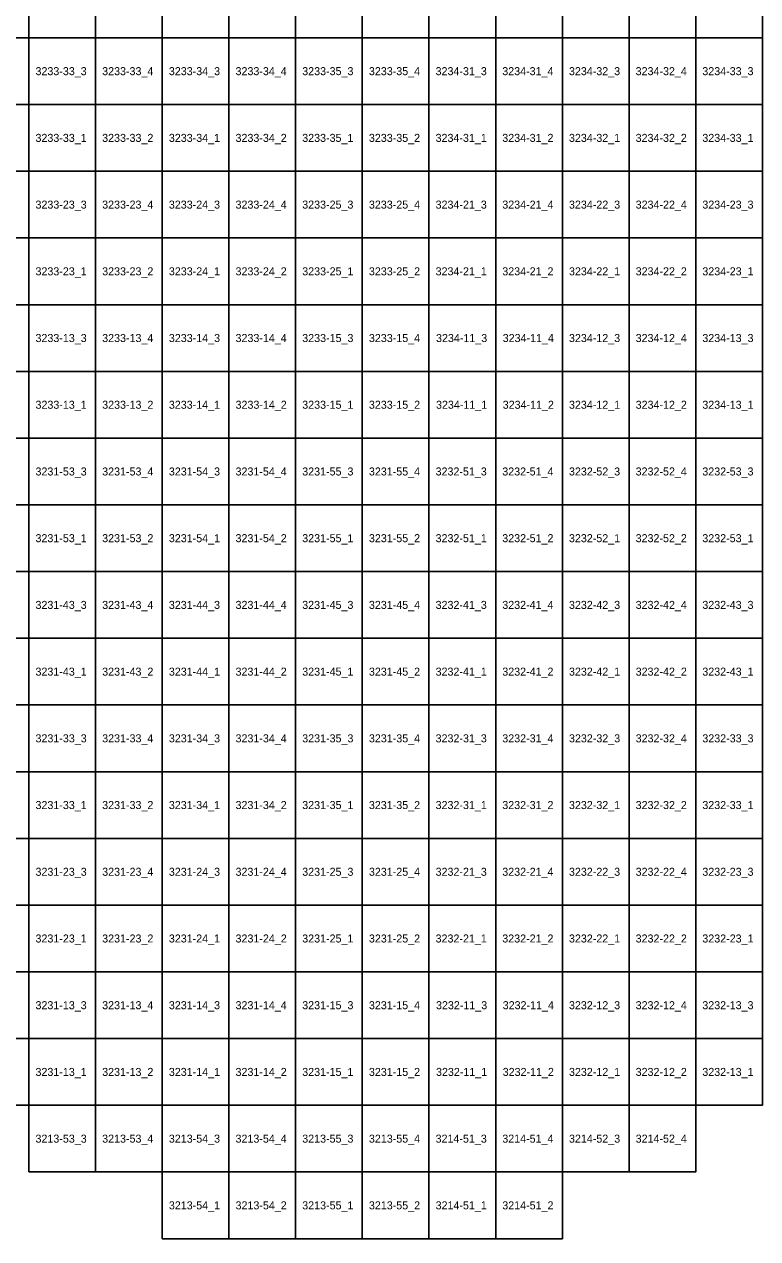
# Model space of a CAD drawing. Extents: x 312500 to 765000, y 172500 to 440000.
# Drawn here: x 409827 to 437325, y 245000 to 290507 of the extents above; entities that cross this region are included whole.
import ezdxf

# ---------------------------------------------------------------- set-up
doc = ezdxf.new("R2010")
doc.units = 0
doc.layers.add('Topo5_ramis_TKS2025', color=7, linetype='Continuous')
doc.layers.add('Topo5_ramis_TKS2025_Nr', color=7, linetype='Continuous')

msp = doc.modelspace()

# ---------------------------------------------------------------- linework, layer by layer
at = {"layer": 'Topo5_ramis_TKS2025'}
for points in [[(407500, 290000), (407500, 292500), (410000, 292500), (410000, 290000), (407500, 290000)], [(410000, 290000), (410000, 292500), (412500, 292500), (412500, 290000), (410000, 290000)], [(412500, 290000), (412500, 292500), (415000, 292500), (415000, 290000), (412500, 290000)], [(415000, 290000), (415000, 292500), (417500, 292500), (417500, 290000), (415000, 290000)], [(417500, 290000), (417500, 292500), (420000, 292500), (420000, 290000), (417500, 290000)], [(420000, 290000), (420000, 292500), (422500, 292500), (422500, 290000), (420000, 290000)], [(422500, 290000), (422500, 292500), (425000, 292500), (425000, 290000), (422500, 290000)], [(425000, 290000), (425000, 292500), (427500, 292500), (427500, 290000), (425000, 290000)], [(427500, 290000), (427500, 292500), (430000, 292500), (430000, 290000), (427500, 290000)], [(430000, 290000), (430000, 292500), (432500, 292500), (432500, 290000), (430000, 290000)], [(432500, 290000), (432500, 292500), (435000, 292500), (435000, 290000), (432500, 290000)], [(435000, 290000), (435000, 292500), (437500, 292500), (437500, 290000), (435000, 290000)], [(407500, 287500), (407500, 290000), (410000, 290000), (410000, 287500), (407500, 287500)], [(410000, 287500), (410000, 290000), (412500, 290000), (412500, 287500), (410000, 287500)], [(412500, 287500), (412500, 290000), (415000, 290000), (415000, 287500), (412500, 287500)], [(415000, 287500), (415000, 290000), (417500, 290000), (417500, 287500), (415000, 287500)], [(417500, 287500), (417500, 290000), (420000, 290000), (420000, 287500), (417500, 287500)], [(420000, 287500), (420000, 290000), (422500, 290000), (422500, 287500), (420000, 287500)], [(422500, 287500), (422500, 290000), (425000, 290000), (425000, 287500), (422500, 287500)], [(425000, 287500), (425000, 290000), (427500, 290000), (427500, 287500), (425000, 287500)], [(427500, 287500), (427500, 290000), (430000, 290000), (430000, 287500), (427500, 287500)], [(430000, 287500), (430000, 290000), (432500, 290000), (432500, 287500), (430000, 287500)], [(432500, 287500), (432500, 290000), (435000, 290000), (435000, 287500), (432500, 287500)], [(435000, 287500), (435000, 290000), (437500, 290000), (437500, 287500), (435000, 287500)], [(407500, 285000), (407500, 287500), (410000, 287500), (410000, 285000), (407500, 285000)], [(410000, 285000), (410000, 287500), (412500, 287500), (412500, 285000), (410000, 285000)], [(412500, 285000), (412500, 287500), (415000, 287500), (415000, 285000), (412500, 285000)], [(415000, 285000), (415000, 287500), (417500, 287500), (417500, 285000), (415000, 285000)], [(417500, 285000), (417500, 287500), (420000, 287500), (420000, 285000), (417500, 285000)], [(420000, 285000), (420000, 287500), (422500, 287500), (422500, 285000), (420000, 285000)], [(422500, 285000), (422500, 287500), (425000, 287500), (425000, 285000), (422500, 285000)], [(425000, 285000), (425000, 287500), (427500, 287500), (427500, 285000), (425000, 285000)], [(427500, 285000), (427500, 287500), (430000, 287500), (430000, 285000), (427500, 285000)], [(430000, 285000), (430000, 287500), (432500, 287500), (432500, 285000), (430000, 285000)], [(432500, 285000), (432500, 287500), (435000, 287500), (435000, 285000), (432500, 285000)], [(435000, 285000), (435000, 287500), (437500, 287500), (437500, 285000), (435000, 285000)], [(407500, 282500), (407500, 285000), (410000, 285000), (410000, 282500), (407500, 282500)], [(410000, 282500), (410000, 285000), (412500, 285000), (412500, 282500), (410000, 282500)], [(412500, 282500), (412500, 285000), (415000, 285000), (415000, 282500), (412500, 282500)], [(415000, 282500), (415000, 285000), (417500, 285000), (417500, 282500), (415000, 282500)], [(417500, 282500), (417500, 285000), (420000, 285000), (420000, 282500), (417500, 282500)], [(420000, 282500), (420000, 285000), (422500, 285000), (422500, 282500), (420000, 282500)], [(422500, 282500), (422500, 285000), (425000, 285000), (425000, 282500), (422500, 282500)], [(425000, 282500), (425000, 285000), (427500, 285000), (427500, 282500), (425000, 282500)], [(427500, 282500), (427500, 285000), (430000, 285000), (430000, 282500), (427500, 282500)], [(430000, 282500), (430000, 285000), (432500, 285000), (432500, 282500), (430000, 282500)], [(432500, 282500), (432500, 285000), (435000, 285000), (435000, 282500), (432500, 282500)], [(435000, 282500), (435000, 285000), (437500, 285000), (437500, 282500), (435000, 282500)], [(407500, 280000), (407500, 282500), (410000, 282500), (410000, 280000), (407500, 280000)], [(410000, 280000), (410000, 282500), (412500, 282500), (412500, 280000), (410000, 280000)], [(412500, 280000), (412500, 282500), (415000, 282500), (415000, 280000), (412500, 280000)], [(415000, 280000), (415000, 282500), (417500, 282500), (417500, 280000), (415000, 280000)], [(417500, 280000), (417500, 282500), (420000, 282500), (420000, 280000), (417500, 280000)], [(420000, 280000), (420000, 282500), (422500, 282500), (422500, 280000), (420000, 280000)], [(422500, 280000), (422500, 282500), (425000, 282500), (425000, 280000), (422500, 280000)], [(425000, 280000), (425000, 282500), (427500, 282500), (427500, 280000), (425000, 280000)], [(427500, 280000), (427500, 282500), (430000, 282500), (430000, 280000), (427500, 280000)], [(430000, 280000), (430000, 282500), (432500, 282500), (432500, 280000), (430000, 280000)], [(432500, 280000), (432500, 282500), (435000, 282500), (435000, 280000), (432500, 280000)], [(435000, 280000), (435000, 282500), (437500, 282500), (437500, 280000), (435000, 280000)], [(407500, 277500), (407500, 280000), (410000, 280000), (410000, 277500), (407500, 277500)], [(410000, 277500), (410000, 280000), (412500, 280000), (412500, 277500), (410000, 277500)], [(412500, 277500), (412500, 280000), (415000, 280000), (415000, 277500), (412500, 277500)], [(415000, 277500), (415000, 280000), (417500, 280000), (417500, 277500), (415000, 277500)], [(417500, 277500), (417500, 280000), (420000, 280000), (420000, 277500), (417500, 277500)], [(420000, 277500), (420000, 280000), (422500, 280000), (422500, 277500), (420000, 277500)], [(422500, 277500), (422500, 280000), (425000, 280000), (425000, 277500), (422500, 277500)], [(425000, 277500), (425000, 280000), (427500, 280000), (427500, 277500), (425000, 277500)], [(427500, 277500), (427500, 280000), (430000, 280000), (430000, 277500), (427500, 277500)], [(430000, 277500), (430000, 280000), (432500, 280000), (432500, 277500), (430000, 277500)], [(432500, 277500), (432500, 280000), (435000, 280000), (435000, 277500), (432500, 277500)], [(435000, 277500), (435000, 280000), (437500, 280000), (437500, 277500), (435000, 277500)], [(407500, 275000), (407500, 277500), (410000, 277500), (410000, 275000), (407500, 275000)], [(410000, 275000), (410000, 277500), (412500, 277500), (412500, 275000), (410000, 275000)], [(412500, 275000), (412500, 277500), (415000, 277500), (415000, 275000), (412500, 275000)], [(415000, 275000), (415000, 277500), (417500, 277500), (417500, 275000), (415000, 275000)], [(417500, 275000), (417500, 277500), (420000, 277500), (420000, 275000), (417500, 275000)], [(420000, 275000), (420000, 277500), (422500, 277500), (422500, 275000), (420000, 275000)], [(422500, 275000), (422500, 277500), (425000, 277500), (425000, 275000), (422500, 275000)], [(425000, 275000), (425000, 277500), (427500, 277500), (427500, 275000), (425000, 275000)], [(427500, 275000), (427500, 277500), (430000, 277500), (430000, 275000), (427500, 275000)], [(430000, 275000), (430000, 277500), (432500, 277500), (432500, 275000), (430000, 275000)], [(432500, 275000), (432500, 277500), (435000, 277500), (435000, 275000), (432500, 275000)], [(435000, 275000), (435000, 277500), (437500, 277500), (437500, 275000), (435000, 275000)], [(407500, 272500), (407500, 275000), (410000, 275000), (410000, 272500), (407500, 272500)], [(410000, 272500), (410000, 275000), (412500, 275000), (412500, 272500), (410000, 272500)], [(412500, 272500), (412500, 275000), (415000, 275000), (415000, 272500), (412500, 272500)], [(415000, 272500), (415000, 275000), (417500, 275000), (417500, 272500), (415000, 272500)], [(417500, 272500), (417500, 275000), (420000, 275000), (420000, 272500), (417500, 272500)], [(420000, 272500), (420000, 275000), (422500, 275000), (422500, 272500), (420000, 272500)], [(422500, 272500), (422500, 275000), (425000, 275000), (425000, 272500), (422500, 272500)], [(425000, 272500), (425000, 275000), (427500, 275000), (427500, 272500), (425000, 272500)], [(427500, 272500), (427500, 275000), (430000, 275000), (430000, 272500), (427500, 272500)], [(430000, 272500), (430000, 275000), (432500, 275000), (432500, 272500), (430000, 272500)], [(432500, 272500), (432500, 275000), (435000, 275000), (435000, 272500), (432500, 272500)], [(435000, 272500), (435000, 275000), (437500, 275000), (437500, 272500), (435000, 272500)], [(407500, 270000), (407500, 272500), (410000, 272500), (410000, 270000), (407500, 270000)], [(410000, 270000), (410000, 272500), (412500, 272500), (412500, 270000), (410000, 270000)], [(412500, 270000), (412500, 272500), (415000, 272500), (415000, 270000), (412500, 270000)], [(415000, 270000), (415000, 272500), (417500, 272500), (417500, 270000), (415000, 270000)], [(417500, 270000), (417500, 272500), (420000, 272500), (420000, 270000), (417500, 270000)], [(420000, 270000), (420000, 272500), (422500, 272500), (422500, 270000), (420000, 270000)], [(422500, 270000), (422500, 272500), (425000, 272500), (425000, 270000), (422500, 270000)], [(425000, 270000), (425000, 272500), (427500, 272500), (427500, 270000), (425000, 270000)], [(427500, 270000), (427500, 272500), (430000, 272500), (430000, 270000), (427500, 270000)], [(430000, 270000), (430000, 272500), (432500, 272500), (432500, 270000), (430000, 270000)], [(432500, 270000), (432500, 272500), (435000, 272500), (435000, 270000), (432500, 270000)], [(435000, 270000), (435000, 272500), (437500, 272500), (437500, 270000), (435000, 270000)], [(407500, 267500), (407500, 270000), (410000, 270000), (410000, 267500), (407500, 267500)], [(410000, 267500), (410000, 270000), (412500, 270000), (412500, 267500), (410000, 267500)], [(412500, 267500), (412500, 270000), (415000, 270000), (415000, 267500), (412500, 267500)], [(415000, 267500), (415000, 270000), (417500, 270000), (417500, 267500), (415000, 267500)], [(417500, 267500), (417500, 270000), (420000, 270000), (420000, 267500), (417500, 267500)], [(420000, 267500), (420000, 270000), (422500, 270000), (422500, 267500), (420000, 267500)], [(422500, 267500), (422500, 270000), (425000, 270000), (425000, 267500), (422500, 267500)], [(425000, 267500), (425000, 270000), (427500, 270000), (427500, 267500), (425000, 267500)], [(427500, 267500), (427500, 270000), (430000, 270000), (430000, 267500), (427500, 267500)], [(430000, 267500), (430000, 270000), (432500, 270000), (432500, 267500), (430000, 267500)], [(432500, 267500), (432500, 270000), (435000, 270000), (435000, 267500), (432500, 267500)], [(435000, 267500), (435000, 270000), (437500, 270000), (437500, 267500), (435000, 267500)], [(407500, 265000), (407500, 267500), (410000, 267500), (410000, 265000), (407500, 265000)], [(410000, 265000), (410000, 267500), (412500, 267500), (412500, 265000), (410000, 265000)], [(412500, 265000), (412500, 267500), (415000, 267500), (415000, 265000), (412500, 265000)], [(415000, 265000), (415000, 267500), (417500, 267500), (417500, 265000), (415000, 265000)], [(417500, 265000), (417500, 267500), (420000, 267500), (420000, 265000), (417500, 265000)], [(420000, 265000), (420000, 267500), (422500, 267500), (422500, 265000), (420000, 265000)], [(422500, 265000), (422500, 267500), (425000, 267500), (425000, 265000), (422500, 265000)], [(425000, 265000), (425000, 267500), (427500, 267500), (427500, 265000), (425000, 265000)], [(427500, 265000), (427500, 267500), (430000, 267500), (430000, 265000), (427500, 265000)], [(430000, 265000), (430000, 267500), (432500, 267500), (432500, 265000), (430000, 265000)], [(432500, 265000), (432500, 267500), (435000, 267500), (435000, 265000), (432500, 265000)], [(435000, 265000), (435000, 267500), (437500, 267500), (437500, 265000), (435000, 265000)], [(407500, 262500), (407500, 265000), (410000, 265000), (410000, 262500), (407500, 262500)], [(410000, 262500), (410000, 265000), (412500, 265000), (412500, 262500), (410000, 262500)], [(412500, 262500), (412500, 265000), (415000, 265000), (415000, 262500), (412500, 262500)], [(415000, 262500), (415000, 265000), (417500, 265000), (417500, 262500), (415000, 262500)], [(417500, 262500), (417500, 265000), (420000, 265000), (420000, 262500), (417500, 262500)], [(420000, 262500), (420000, 265000), (422500, 265000), (422500, 262500), (420000, 262500)], [(422500, 262500), (422500, 265000), (425000, 265000), (425000, 262500), (422500, 262500)], [(425000, 262500), (425000, 265000), (427500, 265000), (427500, 262500), (425000, 262500)], [(427500, 262500), (427500, 265000), (430000, 265000), (430000, 262500), (427500, 262500)], [(430000, 262500), (430000, 265000), (432500, 265000), (432500, 262500), (430000, 262500)], [(432500, 262500), (432500, 265000), (435000, 265000), (435000, 262500), (432500, 262500)], [(435000, 262500), (435000, 265000), (437500, 265000), (437500, 262500), (435000, 262500)], [(407500, 260000), (407500, 262500), (410000, 262500), (410000, 260000), (407500, 260000)], [(410000, 260000), (410000, 262500), (412500, 262500), (412500, 260000), (410000, 260000)], [(412500, 260000), (412500, 262500), (415000, 262500), (415000, 260000), (412500, 260000)], [(415000, 260000), (415000, 262500), (417500, 262500), (417500, 260000), (415000, 260000)], [(417500, 260000), (417500, 262500), (420000, 262500), (420000, 260000), (417500, 260000)], [(420000, 260000), (420000, 262500), (422500, 262500), (422500, 260000), (420000, 260000)], [(422500, 260000), (422500, 262500), (425000, 262500), (425000, 260000), (422500, 260000)], [(425000, 260000), (425000, 262500), (427500, 262500), (427500, 260000), (425000, 260000)], [(427500, 260000), (427500, 262500), (430000, 262500), (430000, 260000), (427500, 260000)], [(430000, 260000), (430000, 262500), (432500, 262500), (432500, 260000), (430000, 260000)], [(432500, 260000), (432500, 262500), (435000, 262500), (435000, 260000), (432500, 260000)], [(435000, 260000), (435000, 262500), (437500, 262500), (437500, 260000), (435000, 260000)], [(407500, 257500), (407500, 260000), (410000, 260000), (410000, 257500), (407500, 257500)], [(410000, 257500), (410000, 260000), (412500, 260000), (412500, 257500), (410000, 257500)], [(412500, 257500), (412500, 260000), (415000, 260000), (415000, 257500), (412500, 257500)], [(415000, 257500), (415000, 260000), (417500, 260000), (417500, 257500), (415000, 257500)], [(417500, 257500), (417500, 260000), (420000, 260000), (420000, 257500), (417500, 257500)], [(420000, 257500), (420000, 260000), (422500, 260000), (422500, 257500), (420000, 257500)], [(422500, 257500), (422500, 260000), (425000, 260000), (425000, 257500), (422500, 257500)], [(425000, 257500), (425000, 260000), (427500, 260000), (427500, 257500), (425000, 257500)], [(427500, 257500), (427500, 260000), (430000, 260000), (430000, 257500), (427500, 257500)], [(430000, 257500), (430000, 260000), (432500, 260000), (432500, 257500), (430000, 257500)], [(432500, 257500), (432500, 260000), (435000, 260000), (435000, 257500), (432500, 257500)], [(435000, 257500), (435000, 260000), (437500, 260000), (437500, 257500), (435000, 257500)], [(407500, 255000), (407500, 257500), (410000, 257500), (410000, 255000), (407500, 255000)], [(410000, 255000), (410000, 257500), (412500, 257500), (412500, 255000), (410000, 255000)], [(412500, 255000), (412500, 257500), (415000, 257500), (415000, 255000), (412500, 255000)], [(415000, 255000), (415000, 257500), (417500, 257500), (417500, 255000), (415000, 255000)], [(417500, 255000), (417500, 257500), (420000, 257500), (420000, 255000), (417500, 255000)], [(420000, 255000), (420000, 257500), (422500, 257500), (422500, 255000), (420000, 255000)], [(422500, 255000), (422500, 257500), (425000, 257500), (425000, 255000), (422500, 255000)], [(425000, 255000), (425000, 257500), (427500, 257500), (427500, 255000), (425000, 255000)], [(427500, 255000), (427500, 257500), (430000, 257500), (430000, 255000), (427500, 255000)], [(430000, 255000), (430000, 257500), (432500, 257500), (432500, 255000), (430000, 255000)], [(432500, 255000), (432500, 257500), (435000, 257500), (435000, 255000), (432500, 255000)], [(435000, 255000), (435000, 257500), (437500, 257500), (437500, 255000), (435000, 255000)], [(407500, 252500), (407500, 255000), (410000, 255000), (410000, 252500), (407500, 252500)], [(410000, 252500), (410000, 255000), (412500, 255000), (412500, 252500), (410000, 252500)], [(412500, 252500), (412500, 255000), (415000, 255000), (415000, 252500), (412500, 252500)], [(415000, 252500), (415000, 255000), (417500, 255000), (417500, 252500), (415000, 252500)], [(417500, 252500), (417500, 255000), (420000, 255000), (420000, 252500), (417500, 252500)], [(420000, 252500), (420000, 255000), (422500, 255000), (422500, 252500), (420000, 252500)], [(422500, 252500), (422500, 255000), (425000, 255000), (425000, 252500), (422500, 252500)], [(425000, 252500), (425000, 255000), (427500, 255000), (427500, 252500), (425000, 252500)], [(427500, 252500), (427500, 255000), (430000, 255000), (430000, 252500), (427500, 252500)], [(430000, 252500), (430000, 255000), (432500, 255000), (432500, 252500), (430000, 252500)], [(432500, 252500), (432500, 255000), (435000, 255000), (435000, 252500), (432500, 252500)], [(435000, 252500), (435000, 255000), (437500, 255000), (437500, 252500), (435000, 252500)], [(407500, 250000), (407500, 252500), (410000, 252500), (410000, 250000), (407500, 250000)], [(410000, 250000), (410000, 252500), (412500, 252500), (412500, 250000), (410000, 250000)], [(412500, 250000), (412500, 252500), (415000, 252500), (415000, 250000), (412500, 250000)], [(415000, 250000), (415000, 252500), (417500, 252500), (417500, 250000), (415000, 250000)], [(417500, 250000), (417500, 252500), (420000, 252500), (420000, 250000), (417500, 250000)], [(420000, 250000), (420000, 252500), (422500, 252500), (422500, 250000), (420000, 250000)], [(422500, 250000), (422500, 252500), (425000, 252500), (425000, 250000), (422500, 250000)], [(425000, 250000), (425000, 252500), (427500, 252500), (427500, 250000), (425000, 250000)], [(427500, 250000), (427500, 252500), (430000, 252500), (430000, 250000), (427500, 250000)], [(430000, 250000), (430000, 252500), (432500, 252500), (432500, 250000), (430000, 250000)], [(432500, 250000), (432500, 252500), (435000, 252500), (435000, 250000), (432500, 250000)], [(435000, 250000), (435000, 252500), (437500, 252500), (437500, 250000), (435000, 250000)], [(410000, 247500), (410000, 250000), (412500, 250000), (412500, 247500), (410000, 247500)], [(412500, 247500), (412500, 250000), (415000, 250000), (415000, 247500), (412500, 247500)], [(415000, 247500), (415000, 250000), (417500, 250000), (417500, 247500), (415000, 247500)], [(417500, 247500), (417500, 250000), (420000, 250000), (420000, 247500), (417500, 247500)], [(420000, 247500), (420000, 250000), (422500, 250000), (422500, 247500), (420000, 247500)], [(422500, 247500), (422500, 250000), (425000, 250000), (425000, 247500), (422500, 247500)], [(425000, 247500), (425000, 250000), (427500, 250000), (427500, 247500), (425000, 247500)], [(427500, 247500), (427500, 250000), (430000, 250000), (430000, 247500), (427500, 247500)], [(430000, 247500), (430000, 250000), (432500, 250000), (432500, 247500), (430000, 247500)], [(432500, 247500), (432500, 250000), (435000, 250000), (435000, 247500), (432500, 247500)], [(415000, 245000), (415000, 247500), (417500, 247500), (417500, 245000), (415000, 245000)], [(417500, 245000), (417500, 247500), (420000, 247500), (420000, 245000), (417500, 245000)], [(420000, 245000), (420000, 247500), (422500, 247500), (422500, 245000), (420000, 245000)], [(422500, 245000), (422500, 247500), (425000, 247500), (425000, 245000), (422500, 245000)], [(425000, 245000), (425000, 247500), (427500, 247500), (427500, 245000), (425000, 245000)], [(427500, 245000), (427500, 247500), (430000, 247500), (430000, 245000), (427500, 245000)]]:
    msp.add_lwpolyline(points, dxfattribs=at)

# ---------------------------------------------------------------- texts
at = {"layer": 'Topo5_ramis_TKS2025_Nr'}
for s, p in [('3233-33_3', (410248, 288600)), ('3233-33_4', (412748, 288600)), ('3233-34_3', (415248, 288600)), ('3233-34_4', (417748, 288600)), ('3233-35_3', (420248, 288600)), ('3233-35_4', (422748, 288600)), ('3234-31_3', (425248, 288600)), ('3234-31_4', (427748, 288600)), ('3234-32_3', (430248, 288600)), ('3234-32_4', (432748, 288600)), ('3234-33_3', (435248, 288600)), ('3233-33_1', (410248, 286100)), ('3233-33_2', (412748, 286100)), ('3233-34_1', (415248, 286100)), ('3233-34_2', (417748, 286100)), ('3233-35_1', (420248, 286100)), ('3233-35_2', (422748, 286100)), ('3234-31_1', (425248, 286100)), ('3234-31_2', (427748, 286100)), ('3234-32_1', (430248, 286100)), ('3234-32_2', (432748, 286100)), ('3234-33_1', (435248, 286100)), ('3233-23_3', (410248, 283600)), ('3233-23_4', (412748, 283600)), ('3233-24_3', (415248, 283600)), ('3233-24_4', (417748, 283600)), ('3233-25_3', (420248, 283600)), ('3233-25_4', (422748, 283600)), ('3234-21_3', (425248, 283600)), ('3234-21_4', (427748, 283600)), ('3234-22_3', (430248, 283600)), ('3234-22_4', (432748, 283600)), ('3234-23_3', (435248, 283600)), ('3233-23_1', (410248, 281100)), ('3233-23_2', (412748, 281100)), ('3233-24_1', (415248, 281100)), ('3233-24_2', (417748, 281100)), ('3233-25_1', (420248, 281100)), ('3233-25_2', (422748, 281100)), ('3234-21_1', (425248, 281100)), ('3234-21_2', (427748, 281100)), ('3234-22_1', (430248, 281100)), ('3234-22_2', (432748, 281100)), ('3234-23_1', (435248, 281100)), ('3233-13_3', (410248, 278600)), ('3233-13_4', (412748, 278600)), ('3233-14_3', (415248, 278600)), ('3233-14_4', (417748, 278600)), ('3233-15_3', (420248, 278600)), ('3233-15_4', (422748, 278600)), ('3234-11_3', (425264, 278600)), ('3234-11_4', (427764, 278600)), ('3234-12_3', (430248, 278600)), ('3234-12_4', (432748, 278600)), ('3234-13_3', (435248, 278600)), ('3233-13_1', (410248, 276100)), ('3233-13_2', (412748, 276100)), ('3233-14_1', (415248, 276100)), ('3233-14_2', (417748, 276100)), ('3233-15_1', (420248, 276100)), ('3233-15_2', (422748, 276100)), ('3234-11_1', (425264, 276100)), ('3234-11_2', (427764, 276100)), ('3234-12_1', (430248, 276100)), ('3234-12_2', (432748, 276100)), ('3234-13_1', (435248, 276100)), ('3231-53_3', (410248, 273600)), ('3231-53_4', (412748, 273600)), ('3231-54_3', (415248, 273600)), ('3231-54_4', (417748, 273600)), ('3231-55_3', (420248, 273600)), ('3231-55_4', (422748, 273600)), ('3232-51_3', (425248, 273600)), ('3232-51_4', (427748, 273600)), ('3232-52_3', (430248, 273600)), ('3232-52_4', (432748, 273600)), ('3232-53_3', (435248, 273600)), ('3231-53_1', (410248, 271100)), ('3231-53_2', (412748, 271100)), ('3231-54_1', (415248, 271100)), ('3231-54_2', (417748, 271100)), ('3231-55_1', (420248, 271100)), ('3231-55_2', (422748, 271100)), ('3232-51_1', (425248, 271100)), ('3232-51_2', (427748, 271100)), ('3232-52_1', (430248, 271100)), ('3232-52_2', (432748, 271100)), ('3232-53_1', (435248, 271100)), ('3231-43_3', (410248, 268600)), ('3231-43_4', (412748, 268600)), ('3231-44_3', (415248, 268600)), ('3231-44_4', (417748, 268600)), ('3231-45_3', (420248, 268600)), ('3231-45_4', (422748, 268600)), ('3232-41_3', (425248, 268600)), ('3232-41_4', (427748, 268600)), ('3232-42_3', (430248, 268600)), ('3232-42_4', (432748, 268600)), ('3232-43_3', (435248, 268600)), ('3231-43_1', (410248, 266100)), ('3231-43_2', (412748, 266100)), ('3231-44_1', (415248, 266100)), ('3231-44_2', (417748, 266100)), ('3231-45_1', (420248, 266100)), ('3231-45_2', (422748, 266100)), ('3232-41_1', (425248, 266100)), ('3232-41_2', (427748, 266100)), ('3232-42_1', (430248, 266100)), ('3232-42_2', (432748, 266100)), ('3232-43_1', (435248, 266100)), ('3231-33_3', (410248, 263600)), ('3231-33_4', (412748, 263600)), ('3231-34_3', (415248, 263600)), ('3231-34_4', (417748, 263600)), ('3231-35_3', (420248, 263600)), ('3231-35_4', (422748, 263600)), ('3232-31_3', (425248, 263600)), ('3232-31_4', (427748, 263600)), ('3232-32_3', (430248, 263600)), ('3232-32_4', (432748, 263600)), ('3232-33_3', (435248, 263600)), ('3231-33_1', (410248, 261100)), ('3231-33_2', (412748, 261100)), ('3231-34_1', (415248, 261100)), ('3231-34_2', (417748, 261100)), ('3231-35_1', (420248, 261100)), ('3231-35_2', (422748, 261100)), ('3232-31_1', (425248, 261100)), ('3232-31_2', (427748, 261100)), ('3232-32_1', (430248, 261100)), ('3232-32_2', (432748, 261100)), ('3232-33_1', (435248, 261100)), ('3231-23_3', (410248, 258600)), ('3231-23_4', (412748, 258600)), ('3231-24_3', (415248, 258600)), ('3231-24_4', (417748, 258600)), ('3231-25_3', (420248, 258600)), ('3231-25_4', (422748, 258600)), ('3232-21_3', (425248, 258600)), ('3232-21_4', (427748, 258600)), ('3232-22_3', (430248, 258600)), ('3232-22_4', (432748, 258600)), ('3232-23_3', (435248, 258600)), ('3231-23_1', (410248, 256100)), ('3231-23_2', (412748, 256100)), ('3231-24_1', (415248, 256100)), ('3231-24_2', (417748, 256100)), ('3231-25_1', (420248, 256100)), ('3231-25_2', (422748, 256100)), ('3232-21_1', (425248, 256100)), ('3232-21_2', (427748, 256100)), ('3232-22_1', (430248, 256100)), ('3232-22_2', (432748, 256100)), ('3232-23_1', (435248, 256100)), ('3231-13_3', (410248, 253600)), ('3231-13_4', (412748, 253600)), ('3231-14_3', (415248, 253600)), ('3231-14_4', (417748, 253600)), ('3231-15_3', (420248, 253600)), ('3231-15_4', (422748, 253600)), ('3232-11_3', (425264, 253600)), ('3232-11_4', (427764, 253600)), ('3232-12_3', (430248, 253600)), ('3232-12_4', (432748, 253600)), ('3232-13_3', (435248, 253600)), ('3231-13_1', (410248, 251100)), ('3231-13_2', (412748, 251100)), ('3231-14_1', (415248, 251100)), ('3231-14_2', (417748, 251100)), ('3231-15_1', (420248, 251100)), ('3231-15_2', (422748, 251100)), ('3232-11_1', (425264, 251100)), ('3232-11_2', (427764, 251100)), ('3232-12_1', (430248, 251100)), ('3232-12_2', (432748, 251100)), ('3232-13_1', (435248, 251100)), ('3213-53_3', (410248, 248600)), ('3213-53_4', (412748, 248600)), ('3213-54_3', (415248, 248600)), ('3213-54_4', (417748, 248600)), ('3213-55_3', (420248, 248600)), ('3213-55_4', (422748, 248600)), ('3214-51_3', (425248, 248600)), ('3214-51_4', (427748, 248600)), ('3214-52_3', (430248, 248600)), ('3214-52_4', (432748, 248600)), ('3213-54_1', (415248, 246100)), ('3213-54_2', (417748, 246100)), ('3213-55_1', (420248, 246100)), ('3213-55_2', (422748, 246100)), ('3214-51_1', (425248, 246100)), ('3214-51_2', (427748, 246100))]:
    msp.add_text(s, height=300, dxfattribs=at).set_placement(p)

doc.saveas('drawing.dxf')
